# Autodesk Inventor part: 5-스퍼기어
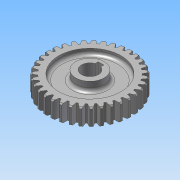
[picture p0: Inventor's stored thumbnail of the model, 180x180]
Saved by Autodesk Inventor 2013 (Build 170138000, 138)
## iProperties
Created: 2013-08
Part Number: 5-스퍼기어
Material: 강
Document SubType Name: Modeling
Designer: 한국산업디자인학원
Categories: <?xml version="1.0" encoding="UTF-16"?> <MemberInstance><Categories><FamilyTemplate><FamilyTemplateParameter ValueType="xs:double" Id="1" ObjectReferenceKey="da
Density: 1 g/cm^3
CustomPartVersion: 1
Author: 한국산업디자인학원
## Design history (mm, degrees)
sketch "Sketch1"
  geometry: C1 r 37 at (0, 0)
  constraints: 1 centre point
  dimensions: "d0" = 74 diameter of C1 (= da_da)
extrude "Extrusion1" new body sketch "Sketch1" distance "d1" = 15 (= da_b); taper "d2" = 0 deg
chamfer "모따기1" distance "d49" = 1; stored, may be unused: second distance "d50" = 2, angle "d51" = 45 deg
workplane "Work Plane2"
feature "피치 지름" dims "d4" = 10, "d5" = 0
workplane "Work Plane8"
workplane "Work Plane9"
feature "스퍼 기어" dims "da_b" = 15, "da_d" = 70, "da_aw" = 70, "da_da" = 74, "da_df" = 65, "da_dw" = 70, angle "da_beta" = 0 deg, "da_lefttooth" = 0, "da_righttooth" = 0
sketch "스케치3"
  geometry: C1 r 12.5 at (0, 0); C2 r 27.5 at (0, 0); A1 r 36 centre (0, 0) between (-30.704, -18.795) and (-29.35, -20.846) reference; A2 r 36 centre (0, 0) between (-5.215, 35.62) and (-7.633, 35.181) reference
  constraints: 2 centre point, 2 coincident
  dimensions: "d52" = 25 diameter of C1; "d54" = 55 diameter of C2
extrude "돌출2" cut sketch "스케치3" distance "d55" = 5; taper "d56" = 0 deg
sketch "스케치4"
  geometry: C1 r 12.5 at (0, 0) reference; C2 r 27.5 at (0, 0) reference
extrude "돌출3" cut sketch "스케치4" distance "d57" = 5; taper "d58" = 0 deg
sketch "스케치5"
  geometry: C1 r 12.5 at (0, 0) reference
extrude "돌출4" join sketch "스케치5" distance "d59" = 3; taper "d60" = 0 deg
node "작업 평면11"
sketch "스케치6"
  geometry: C1 r 12.5 at (0, 0) reference; 1 further point
extrude "돌출5" join sketch "스케치6" distance "d62" = 31; taper "d63" = 0 deg
sketch "스케치7"
  geometry: L1 (-2.5, 7.071)-(-2.5, 9.8); L2 (-2.5, 9.8)-(2.5, 9.8); L3 (2.5, 9.8)-(2.5, 7.071); C1 r 12.5 at (0, 0) reference; A1 r 7.5 centre (0, 0) between (-2.5, 7.071) and (2.5, 7.071); 1 further point
  constraints: 6 end point, 2 point on circle, 1 centre point, 1 coincident, 1 midpoint, 1 parallel, 1 perpendicular, 1 vertical, 1 vertical alignment
  dimensions: "d64" = 15 diameter of A1; "d66" = 5 distance of L1.end L2.end; "d67" = 17.3 dimension on A1 L2
extrude "돌출6" cut sketch "스케치7" stored distance "d68" = 31; taper "d69" = 0 deg
fillet "모깎기1" dims "d70" = 3
body "Solid1"
sketch "Sketch2"
  geometry: C1 r 37 at (0, 0) reference; C2 r 35 at (0, 0)
  constraints: 1 centre point, 1 coincident
  dimensions: "d3" = 70 diameter of C2 (= da_dw)
body "Srf1"
other parameters: "d17" = 0, "d34" = 0.8976 (computed from da_z), "d39" = 0, "d41" = 0, "d47" = 0, "d48" = 0, "d61" = 0
